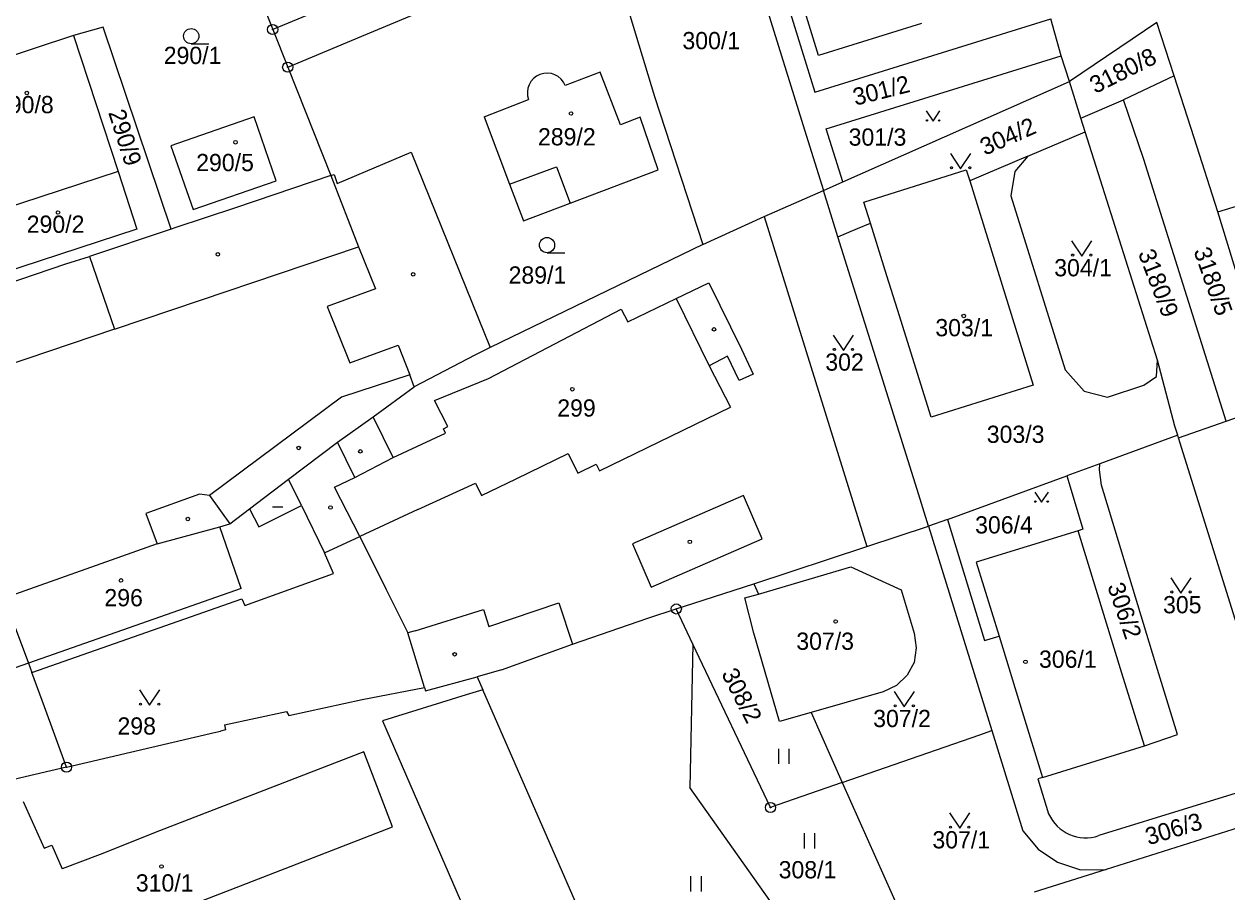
# Model space of a CAD drawing. Extents: x -736345 to -729997, y -1130177 to -1122501.
# Drawn here: x -733663.1 to -733544.4, y -1126639.6 to -1126554 of the extents above; entities that cross this region are included whole.
import ezdxf

# ---------------------------------------------------------------- set-up
doc = ezdxf.new("R2010")
doc.units = 0
for name, color, linetype in [('Vrstva 1', 7, 'Continuous'), ('Vrstva 18', 7, 'Continuous'), ('Vrstva 19', 7, 'Continuous'), ('Vrstva 25', 7, 'Continuous'), ('Vrstva 4', 7, 'Continuous')]:
    doc.layers.add(name, color=color, linetype=linetype)

msp = doc.modelspace()

# ---------------------------------------------------------------- linework, layer by layer
at = {"layer": 'Vrstva 1'}
for points in [[(-733649.04, -1126528.12), (-733638.54, -1126554.54)], [(-733594.57, -1126537.11), (-733585.93, -1126564.94)], [(-733629.74, -1126555.2), (-733605.84, -1126545.21)], [(-733584.72, -1126557.11), (-733587.98, -1126546.49)], [(-733604.98, -1126547.67), (-733600.89, -1126561.13)], [(-733589.36, -1126546.87), (-733585.09, -1126560.72)], [(-733631.3, -1126551.52), (-733638.54, -1126554.54)], [(-733585.09, -1126560.72), (-733561.83, -1126553.47)], [(-733560.79, -1126557.13), (-733561.83, -1126553.47)], [(-733655.25, -1126554.31), (-733658.17, -1126555.13)], [(-733648.56, -1126574.21), (-733655.25, -1126554.31)], [(-733638.54, -1126554.54), (-733637.06, -1126558.25)], [(-733574.56, -1126553.96), (-733584.72, -1126557.11)], [(-733551.35, -1126553.85), (-733559.99, -1126559.66)], [(-733549.66, -1126559.09), (-733551.35, -1126553.85)], [(-733658.17, -1126555.13), (-733666.06, -1126557.74)], [(-733658.17, -1126555.13), (-733653.79, -1126568.52)], [(-733637.06, -1126558.25), (-733629.74, -1126555.2)], [(-733583.96, -1126564.33), (-733560.79, -1126557.13)], [(-733559.99, -1126559.66), (-733560.79, -1126557.13)], [(-733637.06, -1126558.25), (-733632.81, -1126568.94)], [(-733606.25, -1126558.74), (-733609.69, -1126560.06)], [(-733604.26, -1126563.93), (-733606.25, -1126558.74)], [(-733582.32, -1126569.54), (-733559.99, -1126559.66)], [(-733558.85, -1126563.27), (-733559.99, -1126559.66)], [(-733549.66, -1126559.09), (-733554.65, -1126561.48)], [(-733547.69, -1126565.21), (-733549.66, -1126559.09)], [(-733617.68, -1126563.13), (-733613.3, -1126561.45)], [(-733600.89, -1126561.13), (-733596.13, -1126575.74)], [(-733558.85, -1126563.27), (-733554.65, -1126561.48)], [(-733552.66, -1126567.36), (-733554.65, -1126561.48)], [(-733640.38, -1126563.14), (-733648.57, -1126565.99)], [(-733638.2, -1126569.44), (-733640.38, -1126563.14)], [(-733617.68, -1126563.13), (-733615.19, -1126569.8)], [(-733602.32, -1126563.18), (-733604.26, -1126563.93)], [(-733600.52, -1126568.38), (-733602.32, -1126563.18)], [(-733545.34, -1126572.51), (-733511.74, -1126562.29)], [(-733582.32, -1126569.54), (-733583.96, -1126564.33)], [(-733558.42, -1126564.62), (-733558.85, -1126563.27)], [(-733585.93, -1126564.94), (-733584.24, -1126570.4)], [(-733564.08, -1126567.02), (-733558.42, -1126564.62)], [(-733556.92, -1126569.38), (-733558.42, -1126564.62)], [(-733545.34, -1126572.51), (-733547.69, -1126565.21)], [(-733648.57, -1126565.99), (-733646.38, -1126572.29)], [(-733632.18, -1126569.71), (-733624.9, -1126566.63)], [(-733624.9, -1126566.63), (-733617.09, -1126585.87)], [(-733564.08, -1126567.02), (-733569.81, -1126569.46)], [(-733564.08, -1126567.02), (-733565.36, -1126568.53)], [(-733544.53, -1126593.16), (-733552.66, -1126567.36)], [(-733653.79, -1126568.52), (-733667.16, -1126572.92)], [(-733653.79, -1126568.52), (-733651.93, -1126574.22)], [(-733632.81, -1126568.94), (-733642.21, -1126572.12)], [(-733632.81, -1126568.94), (-733632.48, -1126568.82)], [(-733632.48, -1126568.82), (-733632.18, -1126569.71)], [(-733609.22, -1126571.67), (-733600.52, -1126568.38)], [(-733580.25, -1126571.56), (-733570.15, -1126568.38)], [(-733570.15, -1126568.38), (-733569.81, -1126569.46)], [(-733565.36, -1126568.53), (-733565.75, -1126570.95)], [(-733646.38, -1126572.29), (-733638.2, -1126569.44)], [(-733615.19, -1126569.8), (-733613.82, -1126573.4)], [(-733584.24, -1126570.4), (-733582.32, -1126569.54)], [(-733569.81, -1126569.46), (-733563.54, -1126589.6)], [(-733551.3, -1126587.14), (-733556.92, -1126569.38)], [(-733590.08, -1126572.98), (-733584.24, -1126570.4)], [(-733582.81, -1126574.99), (-733584.24, -1126570.4)], [(-733579.6, -1126573.63), (-733580.25, -1126571.56)], [(-733565.75, -1126570.95), (-733560.4, -1126588.09)], [(-733642.21, -1126572.12), (-733648.2, -1126574.09)], [(-733613.82, -1126573.4), (-733609.22, -1126571.67)], [(-733539.57, -1126591.42), (-733545.34, -1126572.51)], [(-733596.13, -1126575.74), (-733590.08, -1126572.98)], [(-733590.08, -1126572.98), (-733579.94, -1126605.5)], [(-733580.88, -1126574.17), (-733579.6, -1126573.63)], [(-733577.97, -1126578.82), (-733579.6, -1126573.63)], [(-733651.93, -1126574.22), (-733665.29, -1126578.59)], [(-733648.56, -1126574.21), (-733656.59, -1126576.91)], [(-733648.2, -1126574.09), (-733648.56, -1126574.21)], [(-733582.81, -1126574.99), (-733580.88, -1126574.17)], [(-733574.99, -1126599.89), (-733582.81, -1126574.99)], [(-733596.13, -1126575.74), (-733617.09, -1126585.87)], [(-733658.94, -1126577.63), (-733656.59, -1126576.91)], [(-733664.92, -1126579.68), (-733658.94, -1126577.63)], [(-733576.93, -1126582.14), (-733577.97, -1126578.82)], [(-733573.6, -1126592.77), (-733576.93, -1126582.14)], [(-733618.6, -1126586.65), (-733624.6, -1126589.77)], [(-733617.09, -1126585.87), (-733618.6, -1126586.65)], [(-733560.4, -1126588.09), (-733558.53, -1126590.2)], [(-733551.39, -1126588.73), (-733551.3, -1126587.14)], [(-733549.58, -1126593.64), (-733551.3, -1126587.14)], [(-733552.66, -1126589.6), (-733551.39, -1126588.73)], [(-733628.63, -1126592.73), (-733624.6, -1126589.77)], [(-733563.54, -1126589.6), (-733573.6, -1126592.77)], [(-733558.53, -1126590.2), (-733556.23, -1126590.78)], [(-733556.23, -1126590.78), (-733552.66, -1126589.6)], [(-733544.53, -1126593.16), (-733539.57, -1126591.42)], [(-733632.15, -1126595.21), (-733628.63, -1126592.73)], [(-733549.3, -1126594.54), (-733549.58, -1126593.64)], [(-733549.22, -1126594.8), (-733544.53, -1126593.16)], [(-733636.97, -1126598.87), (-733632.15, -1126595.21)], [(-733630.45, -1126598.71), (-733632.15, -1126595.21)], [(-733549.3, -1126594.54), (-733556.97, -1126597.34)], [(-733549.22, -1126594.8), (-733549.3, -1126594.54)], [(-733549.06, -1126595.31), (-733549.22, -1126594.8)], [(-733538.73, -1126628.34), (-733549.06, -1126595.31)], [(-733556.97, -1126597.34), (-733560.23, -1126598.53)], [(-733557.03, -1126597.94), (-733556.97, -1126597.34)], [(-733632.45, -1126599.65), (-733630.45, -1126598.71)], [(-733572.01, -1126602.83), (-733560.23, -1126598.53)], [(-733560.23, -1126598.53), (-733560.1, -1126598.95)], [(-733556.83, -1126599.47), (-733557.03, -1126597.94)], [(-733640.81, -1126601.78), (-733636.97, -1126598.87)], [(-733629.96, -1126604.52), (-733632.45, -1126599.65)], [(-733573.87, -1126603.5), (-733574.99, -1126599.89)], [(-733560.1, -1126598.95), (-733558.65, -1126603.8)], [(-733551.56, -1126616.77), (-733556.83, -1126599.47)], [(-733642.76, -1126603.26), (-733640.81, -1126601.78)], [(-733649.94, -1126605.24), (-733643.75, -1126603.55)], [(-733643.75, -1126603.55), (-733642.76, -1126603.26)], [(-733579.94, -1126605.5), (-733573.87, -1126603.5)], [(-733572.01, -1126602.83), (-733573.87, -1126603.5)], [(-733573.87, -1126603.5), (-733567.63, -1126623.66)], [(-733572.01, -1126602.83), (-733568.36, -1126614.78)], [(-733633.43, -1126606.14), (-733629.96, -1126604.52)], [(-733629.96, -1126604.52), (-733627.36, -1126609.74)], [(-733559.13, -1126603.95), (-733569.16, -1126607.05)], [(-733558.65, -1126603.8), (-733559.13, -1126603.95)], [(-733554.8, -1126618), (-733559.13, -1126603.95)], [(-733649.94, -1126605.24), (-733665.01, -1126610.6)], [(-733591.1, -1126609.19), (-733579.94, -1126605.5)], [(-733632.54, -1126608.16), (-733633.43, -1126606.14)], [(-733569.16, -1126607.05), (-733566.92, -1126614.34)], [(-733641.3, -1126611.31), (-733632.54, -1126608.16)], [(-733590.65, -1126610.19), (-733581.53, -1126607.52)], [(-733581.53, -1126607.52), (-733576.57, -1126609.78)], [(-733597.02, -1126611.1), (-733591.1, -1126609.19)], [(-733591.1, -1126609.19), (-733590.65, -1126610.19)], [(-733665.01, -1126610.6), (-733662.61, -1126616.99)], [(-733662.29, -1126617.93), (-733641.58, -1126610.68)], [(-733641.58, -1126610.68), (-733641.3, -1126611.31)], [(-733627.36, -1126609.74), (-733625.22, -1126614.03)], [(-733591.97, -1126610.58), (-733590.65, -1126610.19)], [(-733591.09, -1126614.04), (-733591.97, -1126610.58)], [(-733576.57, -1126609.78), (-733575.29, -1126614.05)], [(-733601.56, -1126612.57), (-733598.74, -1126611.66)], [(-733598.74, -1126611.66), (-733597.02, -1126611.1)], [(-733597.1, -1126615.12), (-733598.74, -1126611.66)], [(-733608.98, -1126615.12), (-733601.56, -1126612.57)], [(-733623.56, -1126619.42), (-733625.22, -1126614.03)], [(-733588.57, -1126622.77), (-733591.09, -1126614.04)], [(-733575.29, -1126614.05), (-733575.08, -1126615.48)], [(-733615.97, -1126617.68), (-733608.98, -1126615.12)], [(-733597.1, -1126615.12), (-733597.4, -1126629.25)], [(-733589.46, -1126631.23), (-733597.1, -1126615.12)], [(-733568.36, -1126614.78), (-733566.92, -1126614.34)], [(-733566.92, -1126614.34), (-733564.64, -1126621.76)], [(-733575.08, -1126615.48), (-733575.3, -1126616.93)], [(-733662.61, -1126616.99), (-733677.3, -1126622.13)], [(-733662.61, -1126616.99), (-733662.29, -1126617.93)], [(-733615.97, -1126617.68), (-733618.39, -1126618.35)], [(-733575.3, -1126616.93), (-733575.98, -1126618.2)], [(-733549.34, -1126624.04), (-733551.56, -1126616.77)], [(-733661.05, -1126621.32), (-733662.29, -1126617.93)], [(-733623.46, -1126619.75), (-733618.39, -1126618.35)], [(-733618.39, -1126618.35), (-733617.83, -1126619.63)], [(-733575.98, -1126618.2), (-733577.04, -1126619.22)], [(-733552.59, -1126625.16), (-733554.8, -1126618)], [(-733629.7, -1126620.58), (-733623.56, -1126619.42)], [(-733623.56, -1126619.42), (-733623.46, -1126619.75)], [(-733601.42, -1126657.16), (-733617.83, -1126619.63)], [(-733578.35, -1126619.84), (-733585.45, -1126621.88)], [(-733577.04, -1126619.22), (-733578.35, -1126619.84)], [(-733658.87, -1126627.26), (-733661.05, -1126621.32)], [(-733636.94, -1126622.16), (-733629.7, -1126620.58)], [(-733643.28, -1126623.08), (-733637.17, -1126621.76)], [(-733637.17, -1126621.76), (-733636.94, -1126622.16)], [(-733585.45, -1126621.88), (-733588.57, -1126622.77)], [(-733585.45, -1126621.88), (-733582.38, -1126628.77)], [(-733564.64, -1126621.76), (-733562.64, -1126628.27)], [(-733644.14, -1126623.82), (-733643.67, -1126623.7)], [(-733643.19, -1126623.59), (-733643.67, -1126623.7)], [(-733643.28, -1126623.08), (-733643.19, -1126623.59)], [(-733568.82, -1126624.07), (-733567.63, -1126623.66)], [(-733567.63, -1126623.66), (-733564.57, -1126633.54)], [(-733658.87, -1126627.26), (-733644.14, -1126623.82)], [(-733582.38, -1126628.77), (-733568.82, -1126624.07)], [(-733552.59, -1126625.16), (-733549.34, -1126624.04)], [(-733562.64, -1126628.27), (-733552.59, -1126625.16)], [(-733658.87, -1126627.26), (-733673.91, -1126630.78)], [(-733562.64, -1126628.27), (-733563.11, -1126628.41)], [(-733563.11, -1126628.41), (-733562.04, -1126631.86)], [(-733538.73, -1126628.34), (-733557.07, -1126634.01)], [(-733583.13, -1126649.42), (-733597.4, -1126629.25)], [(-733582.38, -1126628.77), (-733588.72, -1126630.97)], [(-733582.38, -1126628.77), (-733575, -1126645.33)], [(-733588.72, -1126630.97), (-733589.46, -1126631.23)], [(-733537.61, -1126631.43), (-733556.36, -1126637.34)], [(-733564.57, -1126633.54), (-733563.05, -1126635.34)], [(-733563.05, -1126635.34), (-733561.16, -1126636.64)], [(-733561.16, -1126636.64), (-733558.89, -1126637.37)], [(-733556.36, -1126637.34), (-733563.45, -1126639.57)], [(-733558.89, -1126637.37), (-733556.36, -1126637.34)]]:
    msp.add_lwpolyline(points, dxfattribs=at)
for centre, radius, start, end in [((-733611.491, -1126560.766), 1.934, 21.40557, 200.74768), ((-733558.36, -1126630.173), 4.048, 204.62948, 288.58495)]:
    msp.add_arc(centre, radius, start, end, dxfattribs=at)
at = {"layer": 'Vrstva 25'}
for points in [[(-733646.57, -1126555.94), (-733644.82, -1126555.94)], [(-733574.1, -1126562.564), (-733573.43, -1126563.57), (-733572.759, -1126562.564)], [(-733571.71, -1126566.76), (-733570.71, -1126568.26), (-733569.71, -1126566.76)], [(-733559.76, -1126575.37), (-733558.76, -1126576.87), (-733557.76, -1126575.37)], [(-733611.49, -1126576.54), (-733609.74, -1126576.54)], [(-733583.26, -1126584.67), (-733582.26, -1126586.17), (-733581.26, -1126584.67)], [(-733563.4, -1126600.144), (-733562.73, -1126601.15), (-733562.059, -1126600.144)], [(-733638.55, -1126601.6), (-733637.55, -1126601.6)], [(-733549.98, -1126608.59), (-733548.98, -1126610.09), (-733547.98, -1126608.59)], [(-733651.67, -1126619.65), (-733650.67, -1126621.15), (-733649.67, -1126619.65)], [(-733577.27, -1126619.81), (-733576.27, -1126621.31), (-733575.27, -1126619.81)], [(-733588.647, -1126626.945), (-733588.647, -1126625.445)], [(-733587.613, -1126626.945), (-733587.613, -1126625.445)], [(-733571.8, -1126631.77), (-733570.8, -1126633.27), (-733569.8, -1126631.77)], [(-733586.117, -1126635.265), (-733586.117, -1126633.765)], [(-733585.083, -1126635.265), (-733585.083, -1126633.765)], [(-733597.297, -1126639.505), (-733597.297, -1126638.005)], [(-733596.263, -1126639.505), (-733596.263, -1126638.005)]]:
    msp.add_lwpolyline(points, dxfattribs=at)
for centre, radius in [((-733646.57, -1126555.19), 0.75), ((-733638.54, -1126554.54), 0.5), ((-733638.54, -1126554.54), 0.032), ((-733637.06, -1126558.25), 0.5), ((-733637.06, -1126558.25), 0.032), ((-733662.78, -1126560.79), 0.175), ((-733609.12, -1126562.82), 0.175), ((-733574.033, -1126563.503), 0.067), ((-733572.826, -1126563.503), 0.067), ((-733642.21, -1126565.65), 0.175), ((-733571.61, -1126568.16), 0.1), ((-733569.81, -1126568.16), 0.1), ((-733659.71, -1126572.58), 0.175), ((-733611.49, -1126575.79), 0.75), ((-733643.95, -1126576.7), 0.175), ((-733559.66, -1126576.77), 0.1), ((-733557.86, -1126576.77), 0.1), ((-733624.69, -1126578.67), 0.175), ((-733570.4, -1126582.78), 0.175), ((-733595.03, -1126584.1), 0.175), ((-733583.16, -1126586.07), 0.1), ((-733581.36, -1126586.07), 0.1), ((-733609, -1126590), 0.175), ((-733635.97, -1126595.79), 0.175), ((-733629.9, -1126596.13), 0.175), ((-733563.333, -1126601.083), 0.067), ((-733562.126, -1126601.083), 0.067), ((-733632.84, -1126601.66), 0.175), ((-733646.91, -1126602.79), 0.175), ((-733597.41, -1126605.05), 0.175), ((-733653.5, -1126608.85), 0.175), ((-733549.88, -1126609.99), 0.1), ((-733548.08, -1126609.99), 0.1), ((-733598.74, -1126611.66), 0.5), ((-733598.74, -1126611.66), 0.032), ((-733583.03, -1126612.9), 0.175), ((-733620.6, -1126616.13), 0.175), ((-733564.32, -1126616.87), 0.175), ((-733651.57, -1126621.05), 0.1), ((-733649.77, -1126621.05), 0.1), ((-733577.17, -1126621.21), 0.1), ((-733575.37, -1126621.21), 0.1), ((-733658.87, -1126627.26), 0.5), ((-733658.87, -1126627.26), 0.032), ((-733589.46, -1126631.23), 0.5), ((-733589.46, -1126631.23), 0.032), ((-733571.7, -1126633.17), 0.1), ((-733569.9, -1126633.17), 0.1), ((-733649.5, -1126637.05), 0.175)]:
    msp.add_circle(centre, radius, dxfattribs=at)
at = {"layer": 'Vrstva 4'}
for points in [[(-733632.81, -1126568.94), (-733630.07, -1126575.96)], [(-733615.19, -1126569.8), (-733610.56, -1126568.07)], [(-733610.56, -1126568.07), (-733609.22, -1126571.67)], [(-733645.66, -1126581.22), (-733630.07, -1126575.96)], [(-733630.07, -1126575.96), (-733628.39, -1126580.1)], [(-733656.59, -1126576.91), (-733654.14, -1126584.09)], [(-733598.74, -1126581.06), (-733595.53, -1126579.52)], [(-733595.53, -1126579.52), (-733592.3, -1126586.04)], [(-733628.39, -1126580.1), (-733633.17, -1126581.86)], [(-733654.14, -1126584.09), (-733645.66, -1126581.22)], [(-733633.17, -1126581.86), (-733630.92, -1126587.39)], [(-733617.27, -1126588.95), (-733604.17, -1126582.11)], [(-733604.17, -1126582.11), (-733603.53, -1126583.36)], [(-733603.53, -1126583.36), (-733598.74, -1126581.06)], [(-733598.74, -1126581.06), (-733595.49, -1126587.68)], [(-733654.14, -1126584.09), (-733682.22, -1126593.58)], [(-733630.92, -1126587.39), (-733626.15, -1126585.65)], [(-733626.15, -1126585.65), (-733625, -1126588.58)], [(-733593.69, -1126586.75), (-733595.49, -1126587.68)], [(-733592.53, -1126589.13), (-733593.69, -1126586.75)], [(-733592.3, -1126586.04), (-733591.16, -1126588.52)], [(-733595.49, -1126587.68), (-733593.4, -1126591.77)], [(-733625, -1126588.58), (-733631.76, -1126590.79)], [(-733624.6, -1126589.77), (-733625, -1126588.58)], [(-733622.6, -1126591.11), (-733617.27, -1126588.95)], [(-733591.16, -1126588.52), (-733592.53, -1126589.13)], [(-733631.76, -1126590.79), (-733644.78, -1126600.48)], [(-733621.27, -1126593.69), (-733622.6, -1126591.11)], [(-733626.66, -1126596.74), (-733628.63, -1126592.73)], [(-733606.33, -1126598.06), (-733593.4, -1126591.77)], [(-733621.71, -1126593.9), (-733621.27, -1126593.69)], [(-733621.51, -1126594.33), (-733621.71, -1126593.9)], [(-733626.66, -1126596.74), (-733621.51, -1126594.33)], [(-733614.52, -1126598.85), (-733609.42, -1126596.35)], [(-733609.42, -1126596.35), (-733608.45, -1126598.29)], [(-733630.45, -1126598.71), (-733626.66, -1126596.74)], [(-733608.45, -1126598.29), (-733606.66, -1126597.39)], [(-733606.66, -1126597.39), (-733606.33, -1126598.06)], [(-733635.71, -1126601.46), (-733636.97, -1126598.87)], [(-733624.22, -1126601.87), (-733618.53, -1126599.25)], [(-733618.53, -1126599.25), (-733617.96, -1126600.48)], [(-733617.96, -1126600.48), (-733614.52, -1126598.85)], [(-733645.77, -1126600.34), (-733651.04, -1126602.26)], [(-733644.78, -1126600.48), (-733645.77, -1126600.34)], [(-733644.78, -1126600.48), (-733642.76, -1126603.26)], [(-733592.11, -1126600.47), (-733603.07, -1126605.24)], [(-733590.27, -1126604.75), (-733592.11, -1126600.47)], [(-733651.04, -1126602.26), (-733649.94, -1126605.24)], [(-733640.81, -1126601.78), (-733639.9, -1126603.56)], [(-733639.9, -1126603.56), (-733635.71, -1126601.46)], [(-733635.71, -1126601.46), (-733633.43, -1126606.14)], [(-733624.22, -1126601.87), (-733629.96, -1126604.52)], [(-733641.63, -1126609.63), (-733643.75, -1126603.55)], [(-733601.22, -1126609.53), (-733590.27, -1126604.75)], [(-733603.07, -1126605.24), (-733601.22, -1126609.53)], [(-733641.63, -1126609.63), (-733662.61, -1126616.99)], [(-733624.49, -1126613.82), (-733617.76, -1126611.71)], [(-733617.76, -1126611.71), (-733617.22, -1126613.39)], [(-733617.22, -1126613.39), (-733610.33, -1126611.05)], [(-733610.33, -1126611.05), (-733608.98, -1126615.12)], [(-733624.49, -1126613.82), (-733625.22, -1126614.03)], [(-733619.46, -1126620.14), (-733627.7, -1126622.7)], [(-733617.83, -1126619.63), (-733619.46, -1126620.14)], [(-733627.7, -1126622.7), (-733613.91, -1126654.5)], [(-733629.55, -1126625.74), (-733649.7, -1126633.54)], [(-733626.74, -1126633.14), (-733629.55, -1126625.74)], [(-733663.14, -1126630.64), (-733661.08, -1126635.24)], [(-733641.13, -1126638.72), (-733626.74, -1126633.14)], [(-733649.7, -1126633.54), (-733655.55, -1126635.86)], [(-733661.08, -1126635.24), (-733660.3, -1126634.96)], [(-733660.3, -1126634.96), (-733659.29, -1126637.29)], [(-733655.55, -1126635.86), (-733659.29, -1126637.29)], [(-733648.86, -1126641.72), (-733641.13, -1126638.72)]]:
    msp.add_lwpolyline(points, dxfattribs=at)

# ---------------------------------------------------------------- texts
at = {"layer": 'Vrstva 18'}
for s, p in [('300/1', (-733598.14, -1126556.48)), ('290/1', (-733649.28, -1126557.94)), ('301/3', (-733581.75, -1126565.99)), ('304/1', (-733561.48, -1126578.87)), ('289/1', (-733615.28, -1126579.59)), ('302', (-733584.05, -1126588.17)), ('303/3', (-733568.13, -1126595.29)), ('306/4', (-733569.28, -1126604.22)), ('305', (-733550.75, -1126612.09)), ('298', (-733653.84, -1126624.05)), ('307/2', (-733579.33, -1126623.31)), ('307/1', (-733573.49, -1126635.27)), ('308/1', (-733588.65, -1126638.22))]:
    msp.add_text(s, height=1.7, dxfattribs=at).set_placement(p)
for s, rotation, p in [('3180/8', 26.70021, (-733557.432, -1126560.902)), ('301/2', 14.20011, (-733581.086, -1126562.058)), ('290/9', 287.80229, (-733654.769, -1126562.719)), ('304/2', 23.80019, (-733568.318, -1126566.987)), ('3180/9', 291.10231, (-733553.242, -1126576.584)), ('3180/5', 289.5023, (-733547.765, -1126576.351)), ('306/2', 288.9023, (-733556.266, -1126609.404)), ('308/2', 297.30236, (-733594.341, -1126618.045)), ('306/3', 16.80013, (-733552.187, -1126634.971))]:
    msp.add_text(s, height=1.7, rotation=rotation, dxfattribs=at).set_placement(p)
at = {"layer": 'Vrstva 19'}
for s, p in [('290/8', (-733665.82, -1126562.79)), ('289/2', (-733612.38, -1126565.96)), ('290/5', (-733646.08, -1126568.5)), ('290/2', (-733662.79, -1126574.58)), ('303/1', (-733573.2, -1126584.78)), ('299', (-733610.48, -1126592.7)), ('296', (-733655.13, -1126611.4)), ('307/3', (-733586.91, -1126615.69)), ('306/1', (-733562.98, -1126617.46)), ('310/1', (-733652.03, -1126639.52))]:
    msp.add_text(s, height=1.7, dxfattribs=at).set_placement(p)

doc.saveas('drawing.dxf')
